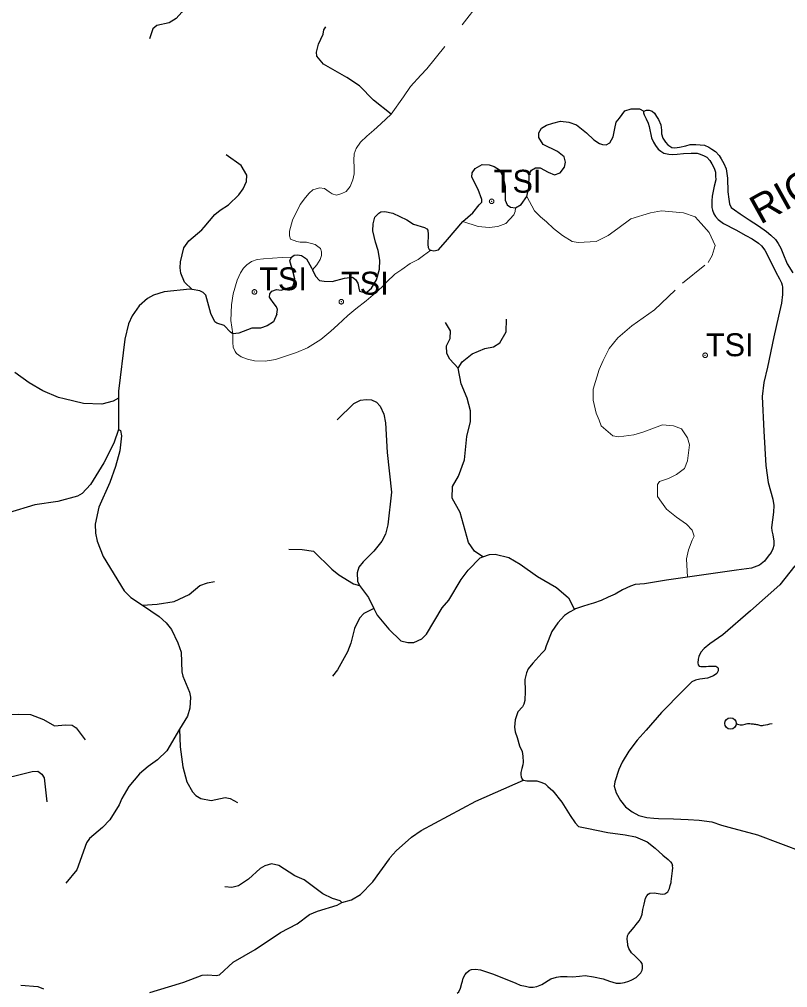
# Model space of a CAD drawing. Extents: x 317.8 to 344.1, y 7676.8 to 7704.8.
# Drawn here: x 325.558 to 328.24, y 7697.935 to 7701.313 of the extents above; entities that cross this region are included whole.
import ezdxf
from ezdxf.enums import TextEntityAlignment as Align

# ---------------------------------------------------------------- set-up
doc = ezdxf.new("R2010")
doc.units = 0
doc.header["$LTSCALE"] = 0.032
doc.header["$PDMODE"] = 32
doc.header["$PDSIZE"] = 0.016
doc.linetypes.add('SHORT_DASHED', pattern=[2.7, 1.5, -1.2])
for name, color, linetype, lineweight in [('2', 7, 'Continuous', 25), ('21', 7, 'SHORT_DASHED', 13), ('22', 7, 'Continuous', 25), ('7', 7, 'Continuous', 25)]:
    doc.layers.add(name, color=color, linetype=linetype, lineweight=lineweight)
doc.layers.add('61', color=7, linetype='Continuous')

msp = doc.modelspace()

# ---------------------------------------------------------------- linework, layer by layer
at = {"layer": '2'}
for points in [[(327.738, 7700.9933), (327.7367, 7700.9909), (327.737, 7700.987), (327.7391, 7700.9799), (327.7459, 7700.9668), (327.7526, 7700.9516), (327.7561, 7700.9399), (327.7645, 7700.9005), (327.7712, 7700.885), (327.7789, 7700.8729), (327.7877, 7700.8607), (327.7966, 7700.853), (327.8076, 7700.8464), (327.8253, 7700.8431), (327.8374, 7700.842), (327.854, 7700.8431), (327.8761, 7700.8453), (327.9026, 7700.8464), (327.9236, 7700.8464), (327.9313, 7700.8442), (327.9457, 7700.8387), (327.9578, 7700.832), (327.9678, 7700.821), (327.9755, 7700.8088), (327.9832, 7700.7945), (327.9877, 7700.7801), (327.9877, 7700.7669), (327.9888, 7700.7536), (327.9832, 7700.7315), (327.9766, 7700.6962), (327.9755, 7700.6807), (327.9755, 7700.6697), (327.9755, 7700.6575), (327.9771, 7700.6479), (327.9815, 7700.6354), (327.9876, 7700.6254), (327.9965, 7700.6155), (328.0153, 7700.6012), (328.0584, 7700.5791), (328.0937, 7700.5592), (328.1158, 7700.5481), (328.1379, 7700.5327), (328.1478, 7700.5227), (328.16, 7700.5084), (328.1732, 7700.4841), (328.1986, 7700.4311), (328.2108, 7700.4079), (328.218, 7700.3942), (328.2208, 7700.3861), (328.2213, 7700.3788)], [(327.738, 7700.9933), (327.7469, 7700.9966), (327.7502, 7700.9966), (327.7557, 7700.9966), (327.7668, 7700.9933), (327.7745, 7700.9856), (327.7822, 7700.9745), (327.7888, 7700.9635), (327.7966, 7700.9458), (327.7999, 7700.927), (327.7999, 7700.9138), (327.8043, 7700.8994), (327.8131, 7700.885), (327.8209, 7700.8751), (327.8352, 7700.8663), (327.8463, 7700.8652), (327.8617, 7700.8674), (327.8838, 7700.8718), (327.8993, 7700.8762), (327.9192, 7700.8773), (327.949, 7700.874), (327.9645, 7700.8674), (327.9744, 7700.8607), (327.9877, 7700.8519), (328.0009, 7700.8387), (328.0075, 7700.8265), (328.0164, 7700.8099), (328.0252, 7700.7923), (328.0296, 7700.7591), (328.0307, 7700.7116), (328.0341, 7700.6862), (328.0363, 7700.6697), (328.0429, 7700.6575), (328.0539, 7700.6487), (328.0738, 7700.6343), (328.1048, 7700.6144), (328.1379, 7700.5934), (328.1655, 7700.5736), (328.181, 7700.5603), (328.1975, 7700.5448), (328.2064, 7700.5316), (328.2163, 7700.515), (328.2229, 7700.4973), (328.2373, 7700.4609), (328.2576, 7700.4284)], [(328.2213, 7700.3788), (328.2214, 7700.3529), (328.2176, 7700.3227), (328.2073, 7700.2783), (328.1912, 7700.2057), (328.1695, 7700.1), (328.1563, 7700.0462), (328.1506, 7699.998), (328.1563, 7699.8763), (328.1629, 7699.7565), (328.1714, 7699.6979), (328.1875, 7699.6394), (328.1912, 7699.6177), (328.1903, 7699.5941), (328.1837, 7699.5403), (328.1846, 7699.529), (328.1884, 7699.5149), (328.1912, 7699.4932), (328.1912, 7699.4781), (328.1875, 7699.4658), (328.1818, 7699.4535), (328.1714, 7699.4403), (328.1582, 7699.4224), (328.1412, 7699.4092), (328.1138, 7699.3988), (328.061, 7699.3912), (327.8903, 7699.3668)], [(328.2651, 7699.4067), (328.2127, 7699.3407), (328.1102, 7699.2496), (328.0134, 7699.1653), (327.9679, 7699.1345), (327.9485, 7699.1186), (327.9371, 7699.1049), (327.9292, 7699.0901), (327.9269, 7699.081), (327.9257, 7699.0685), (327.9269, 7699.0617), (327.9303, 7699.056), (327.936, 7699.0548), (327.9417, 7699.0548), (327.9553, 7699.0548), (327.9633, 7699.056), (327.9736, 7699.056), (327.9815, 7699.0571), (327.9884, 7699.056), (327.9963, 7699.0514), (327.9975, 7699.048), (327.9975, 7699.04), (327.9929, 7699.0309), (327.9804, 7699.0229), (327.9599, 7699.015), (327.9326, 7699.0116), (327.9178, 7699.0081), (327.9052, 7699.0013), (327.8734, 7698.9706), (327.7993, 7698.8943), (327.7458, 7698.8328), (327.7139, 7698.7986), (327.6855, 7698.7599), (327.6615, 7698.7212), (327.6502, 7698.6961), (327.6365, 7698.6528), (327.6342, 7698.638), (327.641, 7698.6141), (327.6559, 7698.5879), (327.6741, 7698.5652), (327.6968, 7698.5481), (327.7208, 7698.5356), (327.7481, 7698.5287), (327.772, 7698.5264), (327.7891, 7698.5253), (327.8415, 7698.5242), (327.8927, 7698.5219), (327.9303, 7698.5196), (327.9747, 7698.5128), (328.0088, 7698.5018)], [(327.8903, 7699.3668), (327.8166, 7699.3563), (327.7401, 7699.344), (327.708, 7699.3412), (327.6911, 7699.3356), (327.6627, 7699.3223), (327.6382, 7699.3082), (327.6137, 7699.2978), (327.5891, 7699.2855), (327.5618, 7699.2761), (327.5457, 7699.2714), (327.5231, 7699.2648), (327.4995, 7699.2563), (327.4961, 7699.2545)], [(327.4961, 7699.2545), (327.4778, 7699.245), (327.4608, 7699.2336), (327.4372, 7699.2082), (327.4164, 7699.177), (327.3966, 7699.1279), (327.3919, 7699.1128), (327.3815, 7699.1015), (327.3504, 7699.0675), (327.3343, 7699.0468), (327.3277, 7699.0336), (327.3221, 7699.01), (327.3239, 7698.9694), (327.3221, 7698.9364), (327.3192, 7698.9241), (327.3145, 7698.9147), (327.2985, 7698.8967), (327.2881, 7698.8694), (327.2862, 7698.8439), (327.289, 7698.8269), (327.2956, 7698.8071), (327.3041, 7698.7788), (327.3136, 7698.7589), (327.3155, 7698.742), (327.3164, 7698.7212), (327.3155, 7698.7118), (327.3117, 7698.6995), (327.3088, 7698.6853), (327.3088, 7698.6778), (327.3098, 7698.6702), (327.3136, 7698.6627), (327.3173, 7698.6589)], [(327.3173, 7698.6589), (327.3296, 7698.657), (327.3494, 7698.657), (327.3645, 7698.6561), (327.3777, 7698.6514), (327.3928, 7698.6457), (327.4032, 7698.6372), (327.4202, 7698.6212), (327.4514, 7698.5825), (327.4806, 7698.5353), (327.4985, 7698.5098), (327.5099, 7698.4966), (327.5382, 7698.4909), (327.6118, 7698.4758), (327.6722, 7698.4683), (327.709, 7698.4607), (327.7496, 7698.4437), (327.7769, 7698.422), (327.8043, 7698.3966), (327.8222, 7698.3815), (327.8307, 7698.3739), (327.8349, 7698.3679), (327.8374, 7698.3598)], [(328.0088, 7698.5018), (328.0345, 7698.4948), (328.1338, 7698.4678), (328.295, 7698.4078), (328.516, 7698.319), (328.6937, 7698.2477), (328.7485, 7698.226), (328.8053, 7698.2116), (328.9169, 7698.1764), (329.0501, 7698.1279), (329.1586, 7698.0824), (329.1976, 7698.0644), (329.3311, 7698.0029), (329.5429, 7697.8954)], [(327.1075, 7697.9682), (327.1138, 7697.9806), (327.1184, 7697.986), (327.1285, 7697.9946), (327.1324, 7697.9969), (327.1363, 7697.9985), (327.1503, 7697.9993), (327.1674, 7697.9969), (327.2133, 7697.9822), (327.2911, 7697.951), (327.3059, 7697.944), (327.3245, 7697.9394), (327.3385, 7697.937), (327.3518, 7697.937), (327.3642, 7697.9386), (327.3813, 7697.9456), (327.3907, 7697.9518), (327.4039, 7697.9596), (327.4132, 7697.965), (327.4334, 7697.9713), (327.4467, 7697.9736), (327.47, 7697.9736), (327.4887, 7697.972), (327.5128, 7697.9744), (327.533, 7697.9767), (327.5618, 7697.9728), (327.596, 7697.965), (327.6178, 7697.9573), (327.6411, 7697.951), (327.6559, 7697.951), (327.6699, 7697.9526), (327.6854, 7697.9573), (327.6963, 7697.9619), (327.7111, 7697.9705), (327.7243, 7697.9837), (327.7267, 7697.9868), (327.7313, 7697.9962), (327.7329, 7698.0016), (327.7329, 7698.0109), (327.7313, 7698.0195), (327.7267, 7698.0249), (327.7166, 7698.035), (327.7064, 7698.0459), (327.6948, 7698.056), (327.6854, 7698.0716), (327.6823, 7698.0817), (327.6816, 7698.0864), (327.68, 7698.1043), (327.6808, 7698.1152), (327.6847, 7698.1222), (327.6917, 7698.1307), (327.7041, 7698.1455), (327.7111, 7698.1548), (327.7212, 7698.1681), (327.7267, 7698.1789), (327.7313, 7698.1914), (327.7344, 7698.2069), (327.7391, 7698.2256), (327.7407, 7698.2365), (327.7438, 7698.2474), (327.7477, 7698.2552), (327.7531, 7698.2614), (327.7586, 7698.2645), (327.7733, 7698.2653), (327.8021, 7698.2614), (327.8107, 7698.2622), (327.8216, 7698.2692), (327.8239, 7698.2738), (327.827, 7698.2808), (327.8301, 7698.2917), (327.8325, 7698.3018), (327.8332, 7698.3049), (327.8379, 7698.3423), (327.8384, 7698.3528), (327.8374, 7698.3598)], [(327.0865, 7697.916), (327.092, 7697.9207), (327.0974, 7697.9332), (327.1021, 7697.9503), (327.1044, 7697.9573), (327.1075, 7697.9682)]]:
    msp.add_lwpolyline(points, dxfattribs=at)
at = {"layer": '21'}
for points in [[(326.8558, 7700.9826), (326.8985, 7701.0428), (326.9236, 7701.0792), (326.9599, 7701.1183), (326.9809, 7701.1406), (327.1038, 7701.2943), (327.1947, 7701.4103)], [(326.5811, 7700.44), (326.5967, 7700.4574), (326.6078, 7700.4756), (326.6134, 7700.4895), (326.6134, 7700.5021), (326.6092, 7700.5133), (326.5911, 7700.5273), (326.5603, 7700.5357), (326.538, 7700.5357), (326.5268, 7700.5385), (326.5044, 7700.5468), (326.5017, 7700.558), (326.5017, 7700.5748), (326.5044, 7700.5874), (326.5114, 7700.6125), (326.538, 7700.667), (326.5575, 7700.6921), (326.5701, 7700.7075), (326.5827, 7700.7187), (326.6064, 7700.7257), (326.6232, 7700.7229), (326.64, 7700.7117), (326.6498, 7700.7047), (326.6651, 7700.7005), (326.6833, 7700.7061), (326.6987, 7700.7131), (326.7126, 7700.7299), (326.7224, 7700.7536), (326.7266, 7700.7746), (326.7266, 7700.7955), (326.7252, 7700.8221), (326.7266, 7700.8444), (326.7336, 7700.8626), (326.749, 7700.885), (326.7713, 7700.9059), (326.7951, 7700.9269), (326.8202, 7700.9492), (326.8558, 7700.9826)], [(327.8903, 7699.3668), (327.8861, 7699.4309), (327.893, 7699.4621), (327.9068, 7699.4967), (327.9138, 7699.5105), (327.9068, 7699.5313), (327.8861, 7699.552), (327.8515, 7699.5763), (327.8169, 7699.6039), (327.7996, 7699.6282), (327.7857, 7699.6489), (327.7857, 7699.6697), (327.7857, 7699.6905), (327.7926, 7699.7008), (327.8238, 7699.7112), (327.8515, 7699.7251), (327.8792, 7699.7458), (327.8895, 7699.7735), (327.8965, 7699.8289), (327.8895, 7699.8531), (327.8688, 7699.8842), (327.8411, 7699.8946), (327.803, 7699.8981), (327.7373, 7699.8739), (327.7027, 7699.8635), (327.6508, 7699.8566), (327.63, 7699.86), (327.5885, 7699.8946), (327.5815, 7699.9154), (327.5712, 7699.9396), (327.5608, 7699.9846), (327.5608, 7700.0227), (327.5815, 7700.0919), (327.5954, 7700.123), (327.6162, 7700.1645), (327.6473, 7700.2026), (327.6957, 7700.2441), (327.7753, 7700.2995), (327.8722, 7700.3929), (327.9622, 7700.4656), (327.976, 7700.4898), (327.9864, 7700.5244), (327.9657, 7700.5694), (327.938, 7700.6006), (327.9172, 7700.6248), (327.8757, 7700.6386), (327.7996, 7700.6456), (327.7615, 7700.6386), (327.6923, 7700.6179), (327.6473, 7700.5833), (327.6127, 7700.559), (327.5712, 7700.5383), (327.5089, 7700.5348), (327.4881, 7700.5383), (327.4535, 7700.559), (327.4224, 7700.5833), (327.3981, 7700.6075), (327.3774, 7700.6248), (327.3566, 7700.6456), (327.3288, 7700.6952)], [(327.2898, 7700.6554), (327.2886, 7700.643), (327.2839, 7700.6317), (327.2563, 7700.6006), (327.2286, 7700.5902), (327.1974, 7700.5867), (327.1594, 7700.5902), (327.1066, 7700.6077)], [(326.9949, 7700.508), (326.9683, 7700.4895), (326.9502, 7700.4756), (326.9222, 7700.4616), (326.8929, 7700.4406), (326.8691, 7700.4239), (326.8412, 7700.3973), (326.823, 7700.3792), (326.7937, 7700.3526), (326.7685, 7700.3317), (326.7322, 7700.3037), (326.7042, 7700.28), (326.6693, 7700.2478), (326.6456, 7700.2255), (326.6106, 7700.1961), (326.5645, 7700.1668), (326.5254, 7700.1514), (326.4807, 7700.1361), (326.4528, 7700.1263), (326.4164, 7700.1207), (326.3787, 7700.1221), (326.355, 7700.1277), (326.3326, 7700.1361), (326.3158, 7700.1472), (326.3116, 7700.1542), (326.3047, 7700.1696), (326.3033, 7700.1864), (326.3033, 7700.1975), (326.3038, 7700.2164)], [(326.3038, 7700.2164), (326.2963, 7700.2632), (326.2991, 7700.3177), (326.3047, 7700.3554), (326.3186, 7700.4029), (326.3298, 7700.4295), (326.341, 7700.4448), (326.3522, 7700.4574), (326.3689, 7700.4686), (326.3885, 7700.4756), (326.4108, 7700.4784), (326.4416, 7700.4798), (326.4751, 7700.4826), (326.5079, 7700.4837)]]:
    msp.add_lwpolyline(points, dxfattribs=at)
for p in [(327.2065, 7700.6786), (326.3788, 7700.3623), (326.6819, 7700.3281), (327.9517, 7700.1413)]:
    msp.add_point(p, dxfattribs=at)
at = {"layer": '22'}
msp.add_circle((328.0403, 7698.8568), 0.02, dxfattribs=at)
msp.add_spline([(328.0603, 7698.8568), (328.0778, 7698.8513), (328.0953, 7698.8558), (328.1118, 7698.8558), (328.1188, 7698.8553), (328.1268, 7698.8538), (328.1343, 7698.8528), (328.1418, 7698.8503), (328.1548, 7698.8503), (328.1853, 7698.8568)], degree=3, dxfattribs=at)
at = {"layer": '7'}
msp.add_line((325.9044, 7699.9919), (325.9042, 7699.8821), dxfattribs=at)
for points in [[(326.2346, 7701.4595), (326.1921, 7701.4276), (326.1253, 7701.338), (326.1059, 7701.3162), (326.0809, 7701.3008), (326.0384, 7701.2925), (326.0239, 7701.2805), (326.0126, 7701.2449)], [(326.8558, 7700.9826), (326.7946, 7701.0316), (326.745, 7701.0814), (326.7014, 7701.1107), (326.6194, 7701.157), (326.5969, 7701.1845), (326.5953, 7701.1988), (326.6029, 7701.2266), (326.6187, 7701.2617), (326.6214, 7701.2774), (326.6279, 7701.2873)], [(327.4473, 7700.9579), (327.4762, 7700.955), (327.5022, 7700.9456), (327.5376, 7700.9175), (327.5629, 7700.8936), (327.5835, 7700.8799), (327.5936, 7700.8763), (327.6066, 7700.8755), (327.6189, 7700.882), (327.6305, 7700.903), (327.637, 7700.9326), (327.6413, 7700.955), (327.6522, 7700.9688), (327.6708, 7700.9938), (327.6933, 7701.001), (327.7222, 7701.001), (327.738, 7700.9933)], [(327.3288, 7700.6952), (327.3368, 7700.7263), (327.3374, 7700.7729), (327.3453, 7700.7867), (327.3598, 7700.7953), (327.3757, 7700.7953), (327.4039, 7700.7802), (327.4263, 7700.7708), (327.4458, 7700.778), (327.4603, 7700.7982), (327.4639, 7700.8156), (327.4592, 7700.8337), (327.4361, 7700.8525), (327.3862, 7700.877), (327.3718, 7700.9009), (327.3718, 7700.9175), (327.3811, 7700.9334), (327.3985, 7700.9442), (327.4202, 7700.9507), (327.4473, 7700.9579)], [(326.1617, 7700.3704), (326.1347, 7700.3959), (326.1217, 7700.4274), (326.1193, 7700.4464), (326.1209, 7700.4668), (326.1324, 7700.5165), (326.1496, 7700.5409), (326.1948, 7700.5795), (326.2028, 7700.5886), (326.2411, 7700.6324), (326.2587, 7700.6482), (326.2886, 7700.666), (326.3245, 7700.7014), (326.3395, 7700.7219), (326.3516, 7700.7472), (326.3521, 7700.77), (326.332, 7700.8031), (326.2807, 7700.8407)], [(327.1066, 7700.6077), (327.1413, 7700.6388), (327.1626, 7700.6663), (327.172, 7700.6757), (327.1727, 7700.6851), (327.159, 7700.7197), (327.138, 7700.7631), (327.1388, 7700.7776), (327.1493, 7700.7935), (327.1739, 7700.8065), (327.1977, 7700.8058), (327.2158, 7700.8), (327.2338, 7700.7884), (327.2454, 7700.7668), (327.2534, 7700.7299), (327.2541, 7700.6988), (327.2541, 7700.6822), (327.2613, 7700.6663), (327.2721, 7700.6576), (327.2898, 7700.6554)], [(327.2898, 7700.6554), (327.31, 7700.667), (327.3288, 7700.6952)], [(326.5811, 7700.44), (326.5916, 7700.4178), (326.6061, 7700.4026), (326.6227, 7700.3998), (326.6502, 7700.399), (326.6928, 7700.4106), (326.7213, 7700.4142), (326.7315, 7700.4055), (326.7394, 7700.3933), (326.743, 7700.3752), (326.7452, 7700.3651), (326.7618, 7700.3607), (326.7719, 7700.3622), (326.7878, 7700.3752), (326.8052, 7700.4048), (326.8153, 7700.4417), (326.816, 7700.4727), (326.8102, 7700.5067), (326.8008, 7700.5363), (326.7922, 7700.5759), (326.7936, 7700.5997), (326.7994, 7700.6235), (326.8124, 7700.6373), (326.8196, 7700.6416), (326.8341, 7700.6431), (326.8623, 7700.6366), (326.9111, 7700.6135), (326.9342, 7700.599), (326.9725, 7700.5875), (326.9805, 7700.5824), (326.9841, 7700.5781), (326.9848, 7700.5629), (326.9841, 7700.5282), (326.9855, 7700.5174), (326.9891, 7700.5109), (326.9949, 7700.508)], [(326.9949, 7700.508), (327.0047, 7700.5058), (327.0206, 7700.5094), (327.0524, 7700.5449), (327.1066, 7700.6077)], [(326.5079, 7700.4837), (326.518, 7700.4902), (326.5289, 7700.4916), (326.5426, 7700.4895), (326.5602, 7700.4778), (326.5779, 7700.4467), (326.5811, 7700.44)], [(326.4575, 7700.2849), (326.4595, 7700.3005), (326.4555, 7700.3104), (326.4447, 7700.3252), (326.4358, 7700.3371), (326.4318, 7700.344), (326.4328, 7700.3559), (326.4397, 7700.3648), (326.4555, 7700.3707), (326.4723, 7700.3687), (326.4931, 7700.3753), (326.5123, 7700.3818), (326.5166, 7700.3919), (326.5195, 7700.4085), (326.513, 7700.4353), (326.5021, 7700.4707), (326.5079, 7700.4837)], [(326.1617, 7700.3704), (326.1535, 7700.3716), (326.0634, 7700.3631), (326.0267, 7700.3508), (326.0057, 7700.3398), (326.0053, 7700.3395), (325.9761, 7700.3135), (325.9521, 7700.2788), (325.9394, 7700.2505), (325.927, 7700.198), (325.9044, 7700.0163), (325.9044, 7699.9919)], [(326.3038, 7700.2164), (326.2951, 7700.2216), (326.2727, 7700.2454), (326.247, 7700.2532), (326.2409, 7700.2579), (326.2265, 7700.2875), (326.2087, 7700.3513), (326.1998, 7700.3606), (326.1885, 7700.3663), (326.1617, 7700.3704)], [(326.4575, 7700.2849), (326.4448, 7700.2584), (326.4236, 7700.2436), (326.3998, 7700.2362), (326.3692, 7700.2358), (326.324, 7700.2179), (326.3038, 7700.2164)], [(327.0892, 7700.096), (327.0604, 7700.1274), (327.0498, 7700.1476), (327.0486, 7700.1745), (327.0615, 7700.1995), (327.0626, 7700.2263), (327.046, 7700.2555)], [(327.0892, 7700.096), (327.1041, 7700.118), (327.1391, 7700.1464), (327.1828, 7700.1649), (327.2126, 7700.1711), (327.2349, 7700.1844), (327.2569, 7700.2233), (327.2579, 7700.2669)], [(325.9044, 7699.9919), (325.8856, 7699.9809), (325.8465, 7699.9711), (325.7823, 7699.9735), (325.7146, 7699.9898), (325.6952, 7699.9945), (325.6409, 7700.0169), (325.5925, 7700.0453), (325.543, 7700.0809)], [(327.1754, 7699.4378), (327.1465, 7699.4581), (327.1257, 7699.4884), (327.0967, 7699.5922), (327.0684, 7699.6433), (327.0697, 7699.6835), (327.0912, 7699.7194), (327.1119, 7699.777), (327.12, 7699.8582), (327.1331, 7699.9104), (327.1332, 7699.9474), (327.1212, 7699.9916), (327.1005, 7700.0414), (327.0892, 7700.096)], [(326.667, 7699.9155), (326.7251, 7699.9736), (326.7493, 7699.9848), (326.7682, 7699.9873), (326.7878, 7699.9857), (326.8047, 7699.9775), (326.8179, 7699.9633), (326.8308, 7699.9355), (326.8364, 7699.9058), (326.8414, 7699.8016), (326.8576, 7699.6636), (326.8445, 7699.5498), (326.8363, 7699.5175), (326.8238, 7699.4928), (326.7957, 7699.4574), (326.7577, 7699.4203), (326.7434, 7699.4018), (326.7371, 7699.3826), (326.738, 7699.3531), (326.7458, 7699.3375)], [(325.9042, 7699.8821), (325.8881, 7699.8348), (325.8537, 7699.7659), (325.8062, 7699.6909), (325.778, 7699.6594), (325.7612, 7699.6497), (325.6927, 7699.6311), (325.6128, 7699.6197), (325.5201, 7699.5917), (325.4466, 7699.5568), (325.3465, 7699.5157), (325.2856, 7699.468)], [(325.9042, 7699.8821), (325.911, 7699.8794), (325.9146, 7699.8603), (325.909, 7699.8084), (325.8944, 7699.7529), (325.8747, 7699.6972), (325.8357, 7699.6113), (325.8226, 7699.5521), (325.8243, 7699.5204), (325.8305, 7699.4925), (325.8513, 7699.4393), (325.9245, 7699.3199), (325.9473, 7699.2963), (325.9883, 7699.269)], [(326.4991, 7699.4642), (326.5458, 7699.4632), (326.5845, 7699.4583), (326.6488, 7699.3949), (326.6737, 7699.375), (326.7249, 7699.3437), (326.7458, 7699.3375)], [(327.1754, 7699.4378), (327.1995, 7699.4459), (327.2191, 7699.4469), (327.2671, 7699.4358), (327.3065, 7699.412), (327.3661, 7699.3697), (327.4333, 7699.3308), (327.4752, 7699.2948), (327.4961, 7699.2545)], [(326.7957, 7699.2574), (326.8066, 7699.2348), (326.8473, 7699.1851), (326.8899, 7699.1448), (326.9143, 7699.1388), (326.9355, 7699.1387), (326.963, 7699.1522), (326.979, 7699.1682), (327.0339, 7699.2606), (327.057, 7699.2864), (327.1002, 7699.3588), (327.1247, 7699.392), (327.166, 7699.4346), (327.1754, 7699.4378)], [(325.9883, 7699.269), (326.0388, 7699.2727), (326.0981, 7699.2821), (326.1507, 7699.3063), (326.1879, 7699.3376), (326.2152, 7699.3477), (326.24, 7699.3525)], [(326.7458, 7699.3375), (326.7771, 7699.2959), (326.7957, 7699.2574)], [(325.9883, 7699.269), (326.0466, 7699.2301), (326.0711, 7699.2081), (326.0889, 7699.184), (326.111, 7699.1384), (326.1227, 7699.1049), (326.1249, 7699.0373), (326.1288, 7699.0213), (326.1521, 7698.9659), (326.1552, 7698.9484), (326.1534, 7698.9099), (326.1447, 7698.8824), (326.1177, 7698.8366)], [(326.7957, 7699.2574), (326.7609, 7699.2401), (326.7457, 7699.2238), (326.7275, 7699.1877), (326.7147, 7699.1363), (326.703, 7699.1062), (326.6684, 7699.0434), (326.6507, 7699.0216)], [(325.2987, 7699.1927), (325.3467, 7699.0931), (325.4128, 7699.0008), (325.4605, 7698.9256), (325.4866, 7698.8954), (325.5027, 7698.8864), (325.5563, 7698.8895), (325.5974, 7698.8877), (325.6424, 7698.8699), (325.6816, 7698.848), (325.7193, 7698.852), (325.7428, 7698.8503), (325.7562, 7698.8416), (325.7884, 7698.7999)], [(326.1177, 7698.8366), (326.0732, 7698.7612), (326.0402, 7698.7295), (326.0077, 7698.7067), (325.9778, 7698.6803), (325.9404, 7698.637), (325.9158, 7698.5944), (325.9071, 7698.573), (325.8737, 7698.5205), (325.8481, 7698.4938), (325.8033, 7698.4552), (325.7926, 7698.4406), (325.7589, 7698.3456), (325.7208, 7698.2995)], [(326.1177, 7698.8366), (326.1193, 7698.7751), (326.1293, 7698.7048), (326.1431, 7698.6526), (326.1629, 7698.6176), (326.1744, 7698.6048), (326.1921, 7698.5944), (326.2279, 7698.5875), (326.2772, 7698.5977), (326.294, 7698.5946), (326.3198, 7698.5807)], [(325.4619, 7698.6698), (325.5384, 7698.6727), (325.603, 7698.6889), (325.6232, 7698.6904), (325.6365, 7698.6795), (325.6449, 7698.667), (325.6547, 7698.5831)], [(326.6837, 7698.2314), (326.7179, 7698.2415), (326.7487, 7698.2597), (326.7922, 7698.304), (326.8496, 7698.3844), (326.8528, 7698.3889), (326.8731, 7698.4127), (326.9267, 7698.4597), (326.9605, 7698.4832), (327.1513, 7698.5859), (327.3173, 7698.6589)], [(326.6837, 7698.2314), (326.6776, 7698.2373), (326.6517, 7698.2455), (326.6177, 7698.2618), (326.5526, 7698.311), (326.5197, 7698.3246), (326.4638, 7698.361), (326.4387, 7698.3669), (326.4151, 7698.3597), (326.3986, 7698.3501), (326.3576, 7698.3129), (326.3236, 7698.2902), (326.3004, 7698.2848), (326.2758, 7698.2864)], [(326.0138, 7697.9182), (326.1175, 7697.9487), (326.1328, 7697.9545), (326.1965, 7697.9787), (326.216, 7697.98), (326.2449, 7697.9767), (326.2563, 7697.9795), (326.3045, 7698.0241), (326.3814, 7698.0675), (326.4692, 7698.1276), (326.5278, 7698.1578), (326.5708, 7698.1898), (326.5984, 7698.2021), (326.667, 7698.2231), (326.6837, 7698.2314)], [(325.5635, 7697.9433), (325.6229, 7697.9383), (325.6428, 7697.9309)]]:
    msp.add_lwpolyline(points, dxfattribs=at)

# ---------------------------------------------------------------- texts
at = {"layer": '61'}
msp.add_text('RIO BENEVENTE', height=0.1, rotation=29.055, dxfattribs=at).set_placement((328.6186, 7700.8598), align=Align.CENTER)
for p in [(327.214, 7700.7085), (326.3955, 7700.3681), (326.6808, 7700.3527), (327.9541, 7700.138)]:
    msp.add_text('TSI', height=0.08, dxfattribs=at).set_placement(p)

doc.saveas('drawing.dxf')
